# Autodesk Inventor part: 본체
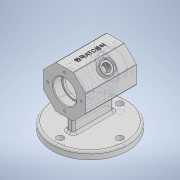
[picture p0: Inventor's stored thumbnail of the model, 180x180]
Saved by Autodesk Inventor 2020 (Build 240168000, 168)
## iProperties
Created: 2021-02
Part Number: 본체
Material: 일반
Document SubType Name: Modeling
Designer: USER
Density: 1 g/cm^3
Appearance: 기본값
Mass: 206.872 g
Surface Area: 501.684 cm^2
Volume: 206.872 cm^3
Author: USER
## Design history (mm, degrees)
sketch "스케치1" dims "d0" = 58
  geometry: L1 (12.012, 29)-(29, 12.012); L2 (29, 12.012)-(29, -12.012); L3 (29, -12.012)-(12.012, -29); L4 (12.012, -29)-(-12.012, -29); L5 (-12.012, -29)-(-29, -12.012); L6 (-29, -12.012)-(-29, 12.012); L7 (-29, 12.012)-(-12.012, 29); L8 (-12.012, 29)-(12.012, 29); 5 further points
  constraints: 16 end point, 2 coincident, 2 midpoint, 1 horizontal alignment, 1 vertical alignment, 19 other
extrude "돌출1" new body sketch "스케치1" distance "d1" = 70; taper "d2" = 0 deg
sketch "스케치2"
  geometry: C1 r 16 at (0, 0); 1 further point
  constraints: 1 centre point, 1 coincident
  dimensions: "d3" = 32 diameter of C1
extrude "돌출2" cut sketch "스케치2" distance "d4" = 12; taper "d5" = 0 deg
sketch "스케치3"
  geometry: L1 (-16, 58)-(16, 58) reference; L2 (12.012, 0)-(-12.012, 0) reference; L3 (0, 58)-(0, 0); L4 (14, 58)-(14, 55); L5 (14, 55)-(22, 55); L6 (22, 55)-(22, 15); L7 (22, 15)-(14, 15); L8 (14, 15)-(14, 12); L9 (14, 12)-(16, 12); L10 (16, 12)-(16, 0); L11 (29, 0)-(12.012, 0) reference
  constraints: 16 end point, 5 perpendicular, 2 point on line, 1 midpoint, 1 vertical
  dimensions: "d6" = 28 diameter of L4 L3; "d7" = 3 distance of L4.start L4.end; "d8" = 44 diameter of L6 L3; "d9" = 40 distance of L5.end L6.end; "d10" = 28 diameter of L8 L3; "d11" = 3 distance of L7.end L8.end; "d12" = 32 diameter of L10 L3
revolve "회전1" sketch "스케치3" stored, may be unused: angle "d13" = 90 deg
node "작업 평면1"
sketch "스케치4"
  geometry: C1 r 52 at (0, 35); 2 further points
  constraints: 1 centre point, 1 coincident, 1 vertical alignment
  dimensions: "d16" = 35 distance of point (0, 0) point (0, 35); "d17" = 104 diameter of C1
extrude "돌출3" join sketch "스케치4" distance "d18" = 10; taper "d19" = 0 deg
sketch "스케치5"
  geometry: L1 (2, -28)-(-2, -28); L2 (-5, -25)-(-5, 25); L3 (-2, 28)-(2, 28); L4 (5, 25)-(5, -25); L5 (5, -28)-(-5, 28); L6 (-5, -28)-(5, 28); C1 r 52 at (0, 0) reference; A1 r 3 centre (-2, 25) between (-2, 28) and (-5, 25); A2 r 3 centre (2, 25) between (5, 25) and (2, 28); A3 r 3 centre (2, -25) between (2, -28) and (5, -25); A4 r 3 centre (-2, -25) between (-5, -25) and (-2, -28); 1 further point
  constraints: 12 end point, 8 point on circle, 8 point on line, 8 tangent, 4 centre point, 3 equal radius, 2 midpoint, 2 parallel, 1 horizontal, 1 perpendicular
  dimensions: "d20" = 10 distance of L5.end L6.end; "d21" = 56 distance of L6.start L5.end; "d22" = 3 radius of A1
extrude "돌출4" join sketch "스케치5" stored distance "d23" = 10; taper "d24" = 0 deg
sketch "스케치7"
  geometry: L1 (0, 70)-(16.988, 70) reference; C1 r 10 at (-12.012, 35); 1 further point
  constraints: 1 centre point
  dimensions: "d26" = 20 diameter of C1; "d27" = 35 distance from line of C1.centre L1; "d28" = 29 horizontal distance of C1.centre L1.end
extrude "돌출5" join sketch "스케치7" distance "d29" = 5; taper "d30" = 0 deg
sketch "스케치8"
  geometry: C1 r 10 at (0, 0) reference; C2 r 8 at (0, 0); 1 further point
  constraints: 1 centre point, 1 coincident
  dimensions: "d31" = 16 diameter of C2
extrude "돌출6" cut sketch "스케치8" distance "d32" = 2; taper "d33" = 0 deg
sketch "스케치9"
  geometry: C1 r 8 at (0, 0) reference; 2 further points
  constraints: 1 coincident
hole "구멍1" sketch "스케치9" at (0, 0) diameter "d34" = 10.917; stored, may be unused: countersink angle "d38" = 90 deg, drill point angle "d40" = 0 deg; dims "d35" = 24, "d36" = 4, "d37" = 2, "d39" = 20
node "작업 평면2"
sketch "스케치11" dims "d41" = 82
  geometry: C1 r 52 at (0, 0) reference; C2 r 4.5 at (-41, 0); 2 further points
  constraints: 2 horizontal alignment, 1 centre point, 1 coincident, 2 other
  dimensions: "d42" = 9 diameter of C2
extrude "돌출7" cut sketch "스케치11" stored distance "d43" = 2; taper "d44" = 0 deg
fillet "모깎기1" dims "d48" = 1
fillet "모깎기2" dims "d49" = 3
fillet "모깎기3" dims "d50" = 0.3
chamfer "모따기1" distance "d51" = 1; stored, may be unused: second distance "d52" = 2, angle "d53" = 45 deg
fillet "모깎기4" dims "d54" = 3
fillet "모깎기5" dims "d55" = 3
fillet "모깎기6" dims "d56" = 3
sketch "스케치12"
  geometry: L1 (23.196, -70)-(0, -70) reference; L2 (-17.109, -70)-(-17.109, 0) reference; 2 further points
  constraints: 1 other
  dimensions: "d57" = 35 distance from line of point (11.891, -35) L1; "d58" = 29 distance from line of point (11.891, -35) L2
feature "엠보싱1" sketch "스케치12" dims "d59" = 0.5, "d60" = 0
chamfer "모따기2" distance "d61" = 1; stored, may be unused: second distance "d62" = 2, angle "d63" = 45 deg
sketch "스케치13"
  geometry: 2 further points
  constraints: 1 vertical alignment
  dimensions: "d64" = 23 distance of point (0, 0) point (0, 23)
hole "구멍2" sketch "스케치13" at (0, 23) diameter "d65" = 3.242; stored, may be unused: countersink angle "d69" = 90 deg, drill point angle "d71" = 118 deg; dims "d66" = 8, "d67" = 4, "d68" = 2, "d70" = 10
node "솔리드1"
pattern_circular "원형 패턴1" dims angle "d46" = 360 deg
pattern_circular "원형 패턴2" dims angle "d73" = 360 deg
mirror "미러1"
node "투영된 루프2"
feature "A9D066F2-1C7D-4E18-AEED-F7BC21143FA4" dims "d34" = 10.917, "d35" = 24, "d36" = 4, "d37" = 2, "d38" = 90 deg, "d39" = 20, "d40" = 0
other parameters: "d14" = -62
